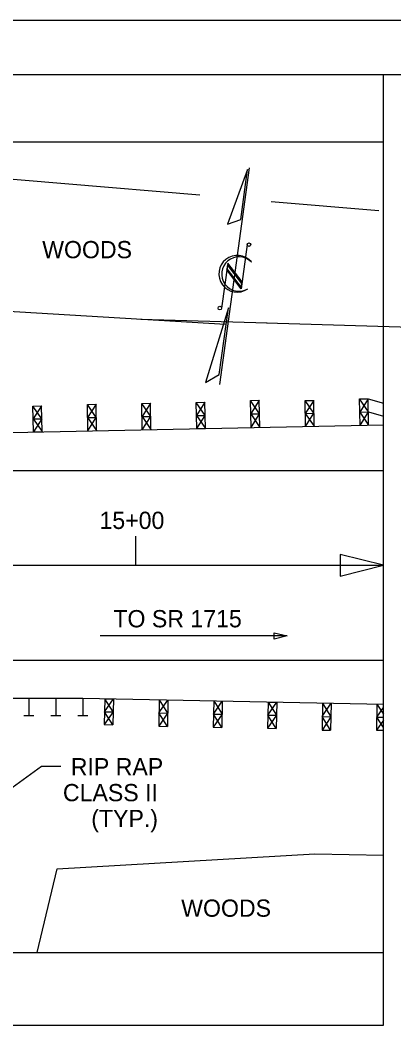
# Model space of a CAD drawing. Extents: x -20 to 509, y -659 to 21.
# Drawn here: x 195.9 to 239.1, y -423.8 to -306.9 of the extents above; entities that cross this region are included whole.
import ezdxf

# ---------------------------------------------------------------- set-up
doc = ezdxf.new("R2010")
doc.units = 0
for name, color, linetype in [('Arrowhead Terminators CELL', 7, 'Continuous'), ('Default', 7, 'Continuous'), ('Dimension Lines', 7, 'Continuous'), ('Exist Vegetation Woods Line', 7, 'Continuous'), ('Plan Sheet CELL', 7, 'Continuous'), ('Plot Shape CELL', 7, 'Continuous'), ('Prop EOT', 7, 'Continuous'), ('Prop Horizontal Alignment', 7, 'Continuous'), ('Prop Horizontal Alignment Tick Large', 7, 'Continuous'), ('Sheet North Arrow CELL', 7, 'Continuous'), ('Text', 7, 'Continuous')]:
    doc.layers.add(name, color=color, linetype=linetype)

msp = doc.modelspace()

# ---------------------------------------------------------------- linework, layer by layer
at = {"layer": 'Arrowhead Terminators CELL'}
for points in [[(237.9, -370.05), (232.9, -368.8), (232.9, -371.3)], [(226.75, -378.24), (225.25, -378.62), (225.25, -377.87)], [(226.75, -378.24), (225.25, -378.62), (225.25, -377.87)]]:
    msp.add_lwpolyline(points, close=True, dxfattribs=at)
at = {"layer": 'Default'}
for p, q in [((197.33, -351.59), (198.33, -351.57)), ((197.39, -354.58), (197.33, -351.59)), ((198.36, -353.06), (197.33, -351.59)), ((198.33, -351.57), (197.36, -353.08)), ((198.39, -354.56), (198.33, -351.57)), ((203.63, -351.41), (204.63, -351.39)), ((203.69, -354.46), (203.63, -351.41)), ((204.66, -352.91), (203.63, -351.41)), ((204.63, -351.39), (203.66, -352.93)), ((204.69, -354.44), (204.63, -351.39)), ((209.93, -351.29), (210.93, -351.27)), ((209.99, -354.33), (209.93, -351.29)), ((210.96, -352.79), (209.93, -351.29)), ((210.93, -351.27), (209.96, -352.81)), ((210.99, -354.31), (210.93, -351.27)), ((216.23, -351.17), (217.23, -351.15)), ((216.29, -354.21), (216.23, -351.17)), ((217.26, -352.67), (216.23, -351.17)), ((217.23, -351.15), (216.26, -352.69)), ((217.29, -354.19), (217.23, -351.15)), ((222.53, -350.94), (223.53, -350.92)), ((222.59, -354.08), (222.53, -350.94)), ((223.56, -352.49), (222.53, -350.94)), ((223.53, -350.92), (222.56, -352.51)), ((223.59, -354.06), (223.53, -350.92)), ((228.83, -350.96), (229.83, -350.94)), ((228.89, -353.95), (228.83, -350.96)), ((229.86, -352.43), (228.83, -350.96)), ((229.83, -350.94), (228.86, -352.45)), ((229.89, -353.93), (229.83, -350.94)), ((235.13, -350.77), (236.13, -350.75)), ((235.19, -353.83), (235.13, -350.77)), ((236.16, -352.28), (235.13, -350.77)), ((236.13, -350.75), (235.16, -352.3)), ((236.19, -353.81), (236.13, -350.75)), ((236.13, -350.75), (237.9, -351.27)), ((197.36, -353.08), (198.36, -353.06)), ((198.36, -353.06), (197.39, -354.58)), ((198.39, -354.56), (198.36, -353.06)), ((203.66, -352.93), (204.66, -352.91)), ((203.66, -352.93), (204.69, -354.44)), ((203.69, -354.46), (204.66, -352.91)), ((209.96, -352.81), (210.96, -352.79)), ((209.96, -352.81), (210.99, -354.31)), ((209.99, -354.33), (210.96, -352.79)), ((216.26, -352.69), (217.26, -352.67)), ((216.26, -352.69), (217.29, -354.19)), ((216.29, -354.21), (217.26, -352.67)), ((222.56, -352.51), (223.56, -352.49)), ((222.56, -352.51), (223.59, -354.06)), ((222.59, -354.08), (223.56, -352.49)), ((228.86, -352.45), (229.86, -352.43)), ((228.86, -352.45), (229.89, -353.93)), ((228.89, -353.95), (229.86, -352.43)), ((235.16, -352.3), (236.16, -352.28)), ((235.16, -352.3), (236.19, -353.81)), ((235.19, -353.83), (236.16, -352.28)), ((236.16, -352.28), (237.9, -352.78)), ((194.85, -354.64), (237.9, -353.77)), ((197.36, -353.08), (198.39, -354.56)), ((216.29, -354.21), (217.29, -354.19)), ((197.39, -354.58), (198.39, -354.56)), ((184.36, -385.47), (203.11, -385.47)), ((196.86, -385.47), (196.86, -387.47)), ((199.98, -385.47), (199.98, -387.47)), ((203.11, -385.47), (203.11, -387.47)), ((203.11, -385.47), (237.9, -386.16)), ((205.65, -385.52), (205.59, -388.52)), ((205.62, -387.02), (206.65, -385.54)), ((205.65, -385.52), (206.65, -385.54)), ((206.62, -387.04), (205.65, -385.52)), ((206.65, -385.54), (206.59, -388.54)), ((206.65, -385.54), (206.62, -387.04)), ((211.95, -385.65), (211.89, -388.7)), ((211.92, -387.17), (212.95, -385.67)), ((211.95, -385.65), (212.92, -387.19)), ((212.95, -385.67), (212.89, -388.72)), ((218.25, -385.77), (218.19, -388.82)), ((218.22, -387.3), (219.25, -385.79)), ((218.25, -385.77), (219.22, -387.32)), ((219.25, -385.79), (219.19, -388.84)), ((224.55, -385.9), (224.49, -388.93)), ((224.52, -387.42), (225.55, -385.92)), ((224.55, -385.9), (225.55, -385.92)), ((224.55, -385.9), (225.52, -387.44)), ((225.55, -385.92), (225.49, -388.95)), ((230.85, -386.02), (230.79, -389.16)), ((230.82, -387.59), (231.85, -386.04)), ((230.85, -386.02), (231.82, -387.61)), ((231.85, -386.04), (231.79, -389.18)), ((237.15, -386.15), (237.09, -389.15)), ((237.12, -387.65), (237.9, -386.54)), ((237.15, -386.15), (237.9, -387.32)), ((196.29, -387.47), (197.43, -387.47)), ((199.41, -387.47), (200.56, -387.47)), ((202.54, -387.47), (203.68, -387.47)), ((206.62, -387.04), (205.59, -388.52)), ((205.62, -387.02), (206.62, -387.04)), ((206.59, -388.54), (205.62, -387.02)), ((212.92, -387.19), (211.89, -388.7)), ((211.92, -387.17), (212.92, -387.19)), ((212.89, -388.72), (211.92, -387.17)), ((219.22, -387.32), (218.19, -388.82)), ((218.22, -387.3), (219.22, -387.32)), ((219.19, -388.84), (218.22, -387.3)), ((225.52, -387.44), (224.49, -388.93)), ((224.52, -387.42), (225.52, -387.44)), ((225.49, -388.95), (224.52, -387.42)), ((231.82, -387.61), (230.79, -389.16)), ((230.82, -387.59), (231.82, -387.61)), ((231.79, -389.18), (230.82, -387.59)), ((237.9, -387.99), (237.09, -389.15)), ((237.12, -387.65), (237.9, -387.67)), ((237.9, -388.86), (237.12, -387.65)), ((205.59, -388.52), (206.59, -388.54)), ((211.89, -388.7), (212.89, -388.72)), ((218.19, -388.82), (219.19, -388.84)), ((224.49, -388.93), (225.49, -388.95)), ((230.79, -389.16), (231.79, -389.18)), ((237.09, -389.15), (237.9, -389.16))]:
    msp.add_line(p, q, dxfattribs=at)
at = {"layer": 'Dimension Lines'}
for p, q in [((226.75, -378.24), (205.13, -378.24)), ((191.55, -398.22), (198.32, -393.34)), ((198.32, -393.34), (200.55, -393.34))]:
    msp.add_line(p, q, dxfattribs=at)
at = {"layer": 'Exist Vegetation Woods Line'}
for points in [[(219.6, -342.15), (168.1, -339.06), (139.97, -337.45), (109.58, -324.44), (104.83, -320.95)], [(185.37, -324.48), (216.64, -327.11)], [(224.9, -327.9), (237.36, -328.94)], [(224.43, -342), (209.81, -341.57)], [(242.44, -342.54), (224.35, -342)], [(197.82, -414.95), (200.15, -405.24), (229.95, -403.49), (237.9, -403.64)]]:
    msp.add_lwpolyline(points, dxfattribs=at)
at = {"layer": 'Plan Sheet CELL'}
for p, q in [((-3.08, -313.17), (508.93, -313.17)), ((-3.08, -320.95), (237.9, -320.95)), ((-3.08, -414.95), (237.9, -414.95))]:
    msp.add_line(p, q, dxfattribs=at)
msp.add_lwpolyline([(-3.08, -423.36), (237.9, -423.36), (237.9, -313.17)], dxfattribs=at)
at = {"layer": 'Plot Shape CELL'}
msp.add_lwpolyline([(-19.94, -306.87), (509.07, -306.87), (509.07, -658.86), (-19.94, -658.86)], close=True, dxfattribs=at)
at = {"layer": 'Prop EOT'}
for p, q in [((-3.08, -359.05), (237.9, -359.05)), ((-3.08, -381.05), (237.9, -381.05))]:
    msp.add_line(p, q, dxfattribs=at)
at = {"layer": 'Prop Horizontal Alignment'}
msp.add_line((70.29, -370.05), (237.9, -370.05), dxfattribs=at)
msp.add_line((70.29, -370.05), (237.9, -370.05), dxfattribs=at)
at = {"layer": 'Prop Horizontal Alignment Tick Large'}
msp.add_line((209.23, -370.05), (209.23, -366.69), dxfattribs=at)
at = {"layer": 'Sheet North Arrow CELL'}
for p, q in [((218.95, -349.1), (222.38, -323.98)), ((222.13, -332.85), (221.43, -338.01)), ((219.88, -335.02), (219.17, -340.26)), ((219.86, -335.21), (219.79, -335.68)), ((221.51, -337.39), (219.86, -335.21)), ((221.54, -337.2), (219.88, -335.02)), ((222.58, -334.87), (222.61, -334.89)), ((221.43, -338.01), (219.77, -335.82)), ((221.45, -337.86), (219.79, -335.68)), ((219.79, -335.68), (221.45, -337.86)), ((221.45, -337.86), (221.51, -337.39))]:
    msp.add_line(p, q, dxfattribs=at)
for points in [[(222.18, -324.18), (219.85, -330.5), (221.39, -329.97)], [(219.95, -340.22), (217.32, -348.88), (218.9, -347.95)]]:
    msp.add_lwpolyline(points, close=True, dxfattribs=at)
for centre in [(222.34, -332.88), (218.96, -340.24)]:
    msp.add_circle(centre, 0.207, dxfattribs=at)
for centre, radius, start, end in [((220.98, -336.26), 2.13, 40.0635, 304.6175), ((221.18, -336.29), 2, 45.3185, 300.8522)]:
    msp.add_arc(centre, radius, start, end, dxfattribs=at)

# ---------------------------------------------------------------- texts
at = {"layer": 'Text'}
for s, p in [('WOODS', (198.4, -334.46)), ('15+00', (205.03, -365.84)), ('TO SR 1715', (206.64, -377.24)), ('RIP RAP', (201.71, -394.4)), ('CLASS II', (200.8, -397.4)), ('(TYP.)', (204.08, -400.4)), ('WOODS', (214.49, -410.79))]:
    msp.add_text(s, height=2, dxfattribs=at).set_placement(p)

doc.saveas('drawing.dxf')
